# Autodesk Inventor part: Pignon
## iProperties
Created: 2008-11
Part Number: Pignon
Document SubType Name: Modeling
Designer: ETUDIANT
Author: ETUDIANT
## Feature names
1. Extrusion1
2. Réseau circulaire1 [Circular Pattern]
3. Extrusion2
4. Miroir1 [Mirror]
5. Extrusion3
6. Chanfrein1 [Chamfer]
